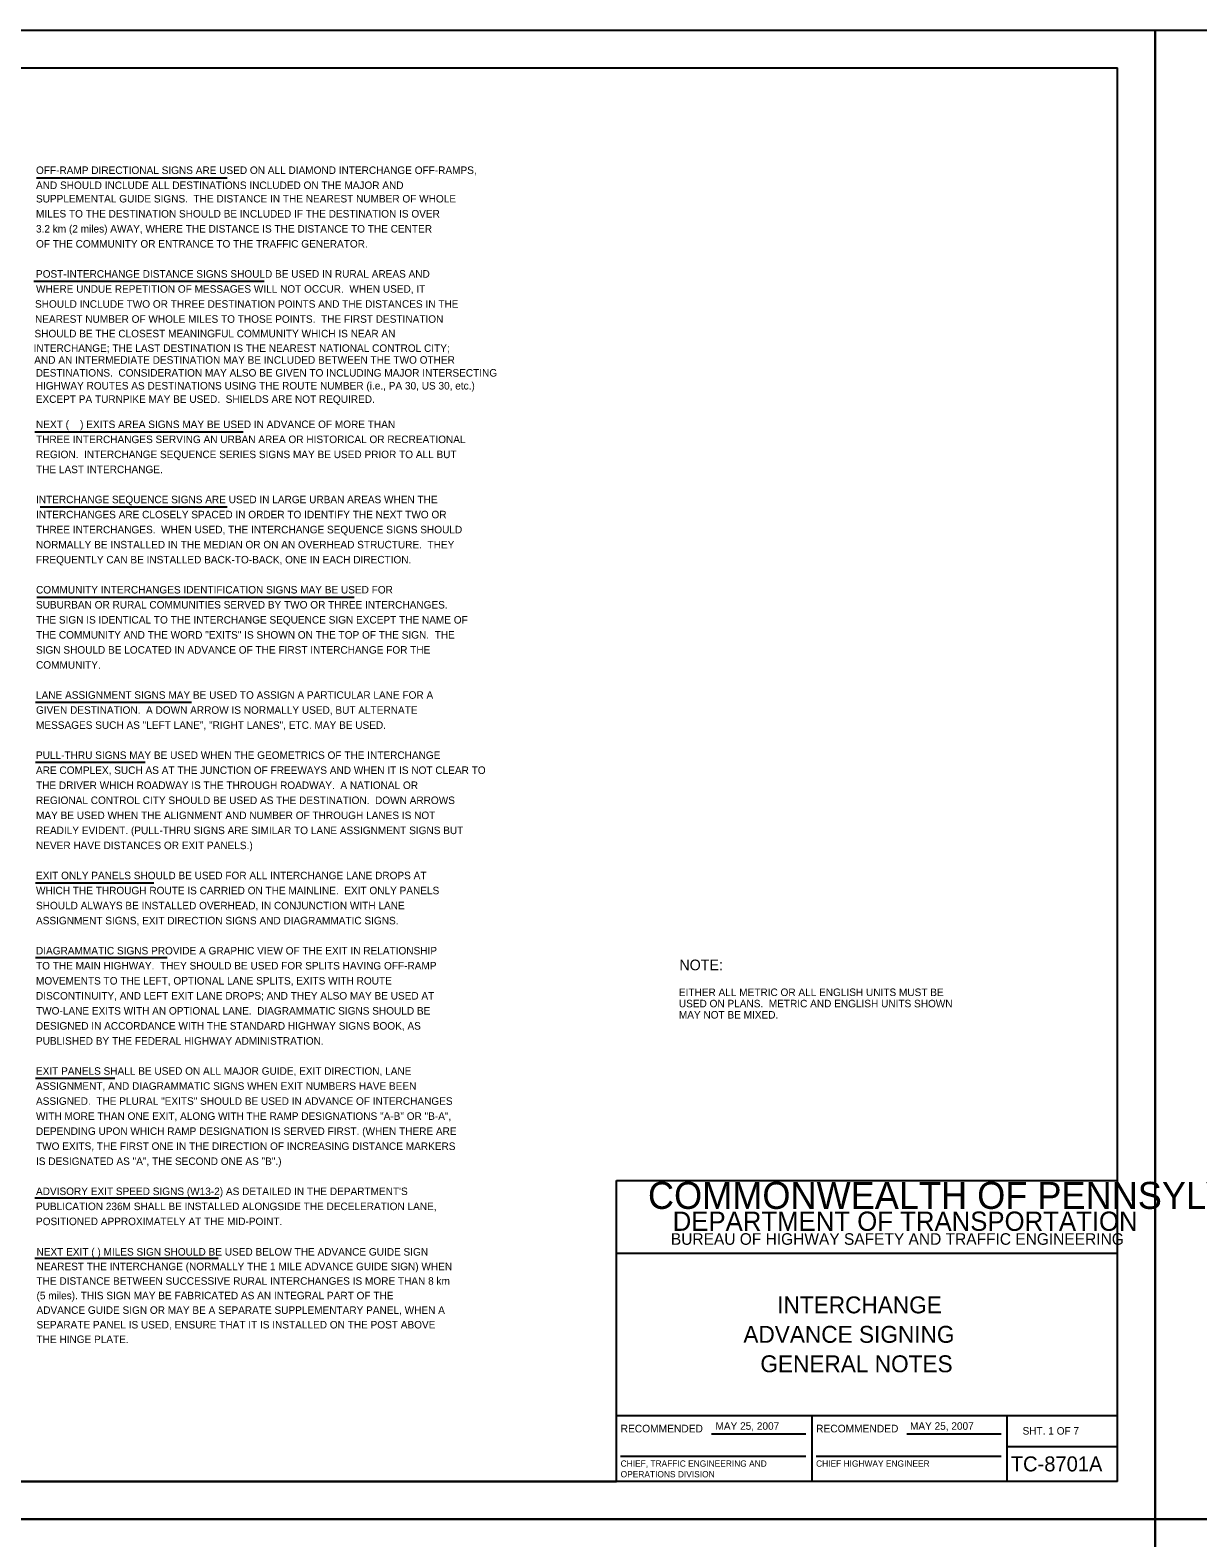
# Model space of a CAD drawing. Extents: x 640994 to 644422, y 298458 to 299646.
# Drawn here: x 641386 to 641852, y 299044 to 299646 of the extents above; entities that cross this region are included whole.
import ezdxf

# ---------------------------------------------------------------- set-up
doc = ezdxf.new("R2010")
doc.units = 0
for name, color, linetype in [('1', 7, 'Continuous'), ('2', 7, 'Continuous'), ('XCS-GRID-MIN', 7, 'Continuous')]:
    doc.layers.add(name, color=color, linetype=linetype)

msp = doc.modelspace()

# ---------------------------------------------------------------- linework, layer by layer
at = {"layer": '1'}
for p, q in [((641034.31, 299630.63), (641820.31, 299630.63)), ((641820.31, 299066.63), (641820.31, 299630.63)), ((641620.31, 299066.63), (641620.31, 299186.63)), ((641620.31, 299186.63), (641820.31, 299186.63)), ((641820.31, 299157.63), (641620.31, 299157.63)), ((641620.31, 299093), (641820.31, 299093)), ((641698.31, 299093), (641698.31, 299066.63)), ((641776.19, 299066.63), (641776.19, 299093)), ((641658.24, 299085.57), (641695.87, 299085.57)), ((641736.24, 299085.57), (641773.87, 299085.57)), ((641776.19, 299080.63), (641820.31, 299080.63)), ((641621.99, 299076.68), (641695.87, 299076.68)), ((641699.99, 299076.68), (641773.87, 299076.68)), ((641820.31, 299066.63), (641034.31, 299066.63)), ((641034.31, 299066.63), (641620.31, 299066.63))]:
    msp.add_line(p, q, dxfattribs=at)
at = {"layer": '2'}
for p, q in [((641388.94, 299586.75), (641464.94, 299586.75)), ((641387.81, 299545.5), (641479.69, 299545.5)), ((641388.19, 299485.38), (641471.31, 299485.38)), ((641390.31, 299455.5), (641464.94, 299455.5)), ((641389.06, 299419.38), (641515.69, 299419.38)), ((641388.44, 299377.5), (641450.69, 299377.5)), ((641388.44, 299353.63), (641432.31, 299353.63)), ((641388.44, 299305.5), (641435.69, 299305.5)), ((641388.44, 299275.63), (641441.06, 299275.63)), ((641388.44, 299227.5), (641420.19, 299227.5)), ((641388.19, 299179.75), (641461.69, 299179.75)), ((641388.19, 299155.75), (641461.32, 299155.75))]:
    msp.add_line(p, q, dxfattribs=at)
at = {"layer": 'XCS-GRID-MIN'}
for points in [[(640994.31, 299645.63), (641835.31, 299645.63), (641835.31, 299051.63), (640994.31, 299051.63)], [(641835.31, 299645.63), (642676.31, 299645.63), (642676.31, 299051.63), (641835.31, 299051.63)], [(640994.31, 299051.63), (641835.31, 299051.63), (641835.31, 298457.63), (640994.31, 298457.63)], [(641835.31, 299051.63), (642676.31, 299051.63), (642676.31, 298457.63), (641835.31, 298457.63)]]:
    msp.add_lwpolyline(points, close=True, dxfattribs=at)

# ---------------------------------------------------------------- texts
at = {"layer": '1'}
for s, height, p in [('COMMONWEALTH OF PENNSYLVANIA', 10.7828, (641632.9, 299175.36)), ('DEPARTMENT OF TRANSPORTATION', 7.6837, (641642.76, 299166.61)), ('BUREAU OF HIGHWAY SAFETY AND TRAFFIC ENGINEERING', 4.6253, (641642.04, 299161.04)), ('INTERCHANGE', 6.75, (641684.49, 299133.69)), ('ADVANCE SIGNING', 6.75, (641670.96, 299121.94)), ('GENERAL NOTES', 6.75, (641677.74, 299110.19)), ('RECOMMENDED', 3.048, (641621.99, 299086.2)), ('RECOMMENDED', 3.048, (641699.99, 299086.2)), ('SHT. 1 OF 7', 3, (641782.4, 299085.31)), ('CHIEF, TRAFFIC ENGINEERING AND', 2.5, (641621.99, 299072.51)), ('CHIEF HIGHWAY ENGINEER', 2.5, (641699.99, 299072.51)), ('TC-8701A', 6, (641777.68, 299070.63)), ('OPERATIONS DIVISION', 2.5, (641621.99, 299068.26))]:
    msp.add_text(s, height=height, dxfattribs=at).set_placement(p)
at = {"layer": '2'}
for s, height, p in [('OFF-RAMP DIRECTIONAL SIGNS ARE USED ON ALL DIAMOND INTERCHANGE OFF-RAMPS,', 3, (641388.69, 299588.25)), ('AND SHOULD INCLUDE ALL DESTINATIONS INCLUDED ON THE MAJOR AND', 3, (641388.69, 299582.25)), ('SUPPLEMENTAL GUIDE SIGNS.  THE DISTANCE IN THE NEAREST NUMBER OF WHOLE', 3, (641388.69, 299576.88)), ('MILES TO THE DESTINATION SHOULD BE INCLUDED IF THE DESTINATION IS OVER ', 3, (641388.69, 299570.88)), ('3.2 km (2 miles) AWAY, WHERE THE DISTANCE IS THE DISTANCE TO THE CENTER ', 3, (641388.69, 299564.88)), ('OF THE COMMUNITY OR ENTRANCE TO THE TRAFFIC GENERATOR.', 3, (641388.69, 299558.88)), ('POST-INTERCHANGE DISTANCE SIGNS SHOULD BE USED IN RURAL AREAS AND', 3, (641388.69, 299546.88)), ('WHERE UNDUE REPETITION OF MESSAGES WILL NOT OCCUR.  WHEN USED, IT', 3, (641388.69, 299540.88)), ('SHOULD INCLUDE TWO OR THREE DESTINATION POINTS AND THE DISTANCES IN THE', 3, (641388.3, 299534.88)), ('NEAREST NUMBER OF WHOLE MILES TO THOSE POINTS.  THE FIRST DESTINATION', 3, (641388.3, 299528.88)), ('SHOULD BE THE CLOSEST MEANINGFUL COMMUNITY WHICH IS NEAR AN', 3, (641388.11, 299523.07)), ('INTERCHANGE; THE LAST DESTINATION IS THE NEAREST NATIONAL CONTROL CITY;', 3, (641387.73, 299517.26)), ('AND AN INTERMEDIATE DESTINATION MAY BE INCLUDED BETWEEN THE TWO OTHER', 3, (641388.01, 299512.55)), ('DESTINATIONS.  CONSIDERATION MAY ALSO BE GIVEN TO INCLUDING MAJOR INTERSECTING', 3, (641388.59, 299507.41)), ('HIGHWAY ROUTES AS DESTINATIONS USING THE ROUTE NUMBER (i.e., PA 30, US 30, etc.)', 3, (641388.59, 299502.26)), ('EXCEPT PA TURNPIKE MAY BE USED.  SHIELDS ARE NOT REQUIRED.', 3, (641388.59, 299496.93)), ('NEXT (    ) EXITS AREA SIGNS MAY BE USED IN ADVANCE OF MORE THAN', 3, (641388.69, 299486.88)), ('THREE INTERCHANGES SERVING AN URBAN AREA OR HISTORICAL OR RECREATIONAL', 3, (641388.69, 299480.88)), ('REGION.  INTERCHANGE SEQUENCE SERIES SIGNS MAY BE USED PRIOR TO ALL BUT', 3, (641388.69, 299474.88)), ('THE LAST INTERCHANGE.', 3, (641388.69, 299468.88)), ('INTERCHANGE SEQUENCE SIGNS ARE USED IN LARGE URBAN AREAS WHEN THE', 3, (641388.69, 299456.88)), ('INTERCHANGES ARE CLOSELY SPACED IN ORDER TO IDENTIFY THE NEXT TWO OR', 3, (641388.69, 299450.88)), ('THREE INTERCHANGES.  WHEN USED, THE INTERCHANGE SEQUENCE SIGNS SHOULD', 3, (641388.69, 299444.88)), ('NORMALLY BE INSTALLED IN THE MEDIAN OR ON AN OVERHEAD STRUCTURE.  THEY', 3, (641388.69, 299438.88)), ('FREQUENTLY CAN BE INSTALLED BACK-TO-BACK, ONE IN EACH DIRECTION.', 3, (641388.69, 299432.88)), ('COMMUNITY INTERCHANGES IDENTIFICATION SIGNS MAY BE USED FOR', 3, (641388.69, 299420.88)), ('SUBURBAN OR RURAL COMMUNITIES SERVED BY TWO OR THREE INTERCHANGES. ', 3, (641388.69, 299414.88)), ('THE SIGN IS IDENTICAL TO THE INTERCHANGE SEQUENCE SIGN EXCEPT THE NAME OF', 3, (641388.69, 299408.88)), ('THE COMMUNITY AND THE WORD "EXITS" IS SHOWN ON THE TOP OF THE SIGN.  THE', 3, (641388.69, 299402.88)), ('SIGN SHOULD BE LOCATED IN ADVANCE OF THE FIRST INTERCHANGE FOR THE', 3, (641388.69, 299396.88)), ('COMMUNITY.', 3, (641388.69, 299390.88)), ('LANE ASSIGNMENT SIGNS MAY BE USED TO ASSIGN A PARTICULAR LANE FOR A', 3, (641388.69, 299378.88)), ('GIVEN DESTINATION.  A DOWN ARROW IS NORMALLY USED, BUT ALTERNATE', 3, (641388.69, 299372.88)), ('MESSAGES SUCH AS "LEFT LANE", "RIGHT LANES", ETC. MAY BE USED.', 3, (641388.69, 299366.88)), ('PULL-THRU SIGNS MAY BE USED WHEN THE GEOMETRICS OF THE INTERCHANGE', 3, (641388.69, 299354.88)), ('ARE COMPLEX, SUCH AS AT THE JUNCTION OF FREEWAYS AND WHEN IT IS NOT CLEAR TO', 3, (641388.69, 299348.88)), ('THE DRIVER WHICH ROADWAY IS THE THROUGH ROADWAY.  A NATIONAL OR', 3, (641388.69, 299342.88)), ('REGIONAL CONTROL CITY SHOULD BE USED AS THE DESTINATION.  DOWN ARROWS', 3, (641388.69, 299336.88)), ('MAY BE USED WHEN THE ALIGNMENT AND NUMBER OF THROUGH LANES IS NOT', 3, (641388.69, 299330.88)), ('READILY EVIDENT. (PULL-THRU SIGNS ARE SIMILAR TO LANE ASSIGNMENT SIGNS BUT', 3, (641388.69, 299324.88)), ('NEVER HAVE DISTANCES OR EXIT PANELS.)', 3, (641388.69, 299318.88)), ('EXIT ONLY PANELS SHOULD BE USED FOR ALL INTERCHANGE LANE DROPS AT', 3, (641388.69, 299306.88)), ('WHICH THE THROUGH ROUTE IS CARRIED ON THE MAINLINE.  EXIT ONLY PANELS', 3, (641388.69, 299300.88)), ('SHOULD ALWAYS BE INSTALLED OVERHEAD, IN CONJUNCTION WITH LANE', 3, (641388.69, 299294.88)), ('ASSIGNMENT SIGNS, EXIT DIRECTION SIGNS AND DIAGRAMMATIC SIGNS.', 3, (641388.69, 299288.88)), ('DIAGRAMMATIC SIGNS PROVIDE A GRAPHIC VIEW OF THE EXIT IN RELATIONSHIP', 3, (641388.69, 299276.88)), ('TO THE MAIN HIGHWAY.  THEY SHOULD BE USED FOR SPLITS HAVING OFF-RAMP', 3, (641388.69, 299270.88)), ('NOTE:', 4.25, (641645.44, 299270.57)), ('MOVEMENTS TO THE LEFT, OPTIONAL LANE SPLITS, EXITS WITH ROUTE', 3, (641388.69, 299264.88)), ('DISCONTINUITY, AND LEFT EXIT LANE DROPS; AND THEY ALSO MAY BE USED AT', 3, (641388.69, 299258.88)), ('USED ON PLANS.  METRIC AND ENGLISH UNITS SHOWN', 3, (641645.23, 299255.79)), ('EITHER ALL METRIC OR ALL ENGLISH UNITS MUST BE', 3, (641645.23, 299260.29)), ('TWO-LANE EXITS WITH AN OPTIONAL LANE.  DIAGRAMMATIC SIGNS SHOULD BE', 3, (641388.69, 299252.88)), ('MAY NOT BE MIXED.', 3, (641645.23, 299251.29)), ('DESIGNED IN ACCORDANCE WITH THE STANDARD HIGHWAY SIGNS BOOK, AS', 3, (641388.69, 299246.88)), ('PUBLISHED BY THE FEDERAL HIGHWAY ADMINISTRATION.', 3, (641388.69, 299240.88)), ('EXIT PANELS SHALL BE USED ON ALL MAJOR GUIDE, EXIT DIRECTION, LANE', 3, (641388.69, 299228.88)), ('ASSIGNMENT, AND DIAGRAMMATIC SIGNS WHEN EXIT NUMBERS HAVE BEEN', 3, (641388.69, 299222.88)), ('ASSIGNED.  THE PLURAL "EXITS" SHOULD BE USED IN ADVANCE OF INTERCHANGES', 3, (641388.69, 299216.88)), ('WITH MORE THAN ONE EXIT, ALONG WITH THE RAMP DESIGNATIONS "A-B" OR "B-A",', 3, (641388.69, 299210.88)), ('DEPENDING UPON WHICH RAMP DESIGNATION IS SERVED FIRST. (WHEN THERE ARE', 3, (641388.69, 299204.88)), ('TWO EXITS, THE FIRST ONE IN THE DIRECTION OF INCREASING DISTANCE MARKERS', 3, (641388.69, 299198.88)), ('IS DESIGNATED AS "A", THE SECOND ONE AS "B".)', 3, (641388.69, 299192.88)), ("ADVISORY EXIT SPEED SIGNS (W13-2) AS DETAILED IN THE DEPARTMENT'S", 3, (641388.69, 299180.88)), ('PUBLICATION 236M SHALL BE INSTALLED ALONGSIDE THE DECELERATION LANE,', 3, (641388.69, 299174.88)), ('POSITIONED APPROXIMATELY AT THE MID-POINT.', 3, (641388.69, 299168.88)), ('NEXT EXIT ( ) MILES SIGN SHOULD BE USED BELOW THE ADVANCE GUIDE SIGN', 3, (641388.9, 299156.73)), ('NEAREST THE INTERCHANGE (NORMALLY THE 1 MILE ADVANCE GUIDE SIGN) WHEN', 3, (641388.9, 299150.91)), ('THE DISTANCE BETWEEN SUCCESSIVE RURAL INTERCHANGES IS MORE THAN 8 km', 3, (641388.9, 299145.1)), ('(5 miles). THIS SIGN MAY BE FABRICATED AS AN INTEGRAL PART OF THE ', 3, (641388.9, 299139.29)), ('ADVANCE GUIDE SIGN OR MAY BE A SEPARATE SUPPLEMENTARY PANEL, WHEN A ', 3, (641388.9, 299133.48)), ('SEPARATE PANEL IS USED, ENSURE THAT IT IS INSTALLED ON THE POST ABOVE ', 3, (641388.9, 299127.66)), ('THE HINGE PLATE.', 3, (641388.9, 299121.85)), ('MAY 25, 2007', 3, (641659.85, 299087.24)), ('MAY 25, 2007', 3, (641737.47, 299087.24))]:
    msp.add_text(s, height=height, dxfattribs=at).set_placement(p)

doc.saveas('drawing.dxf')
